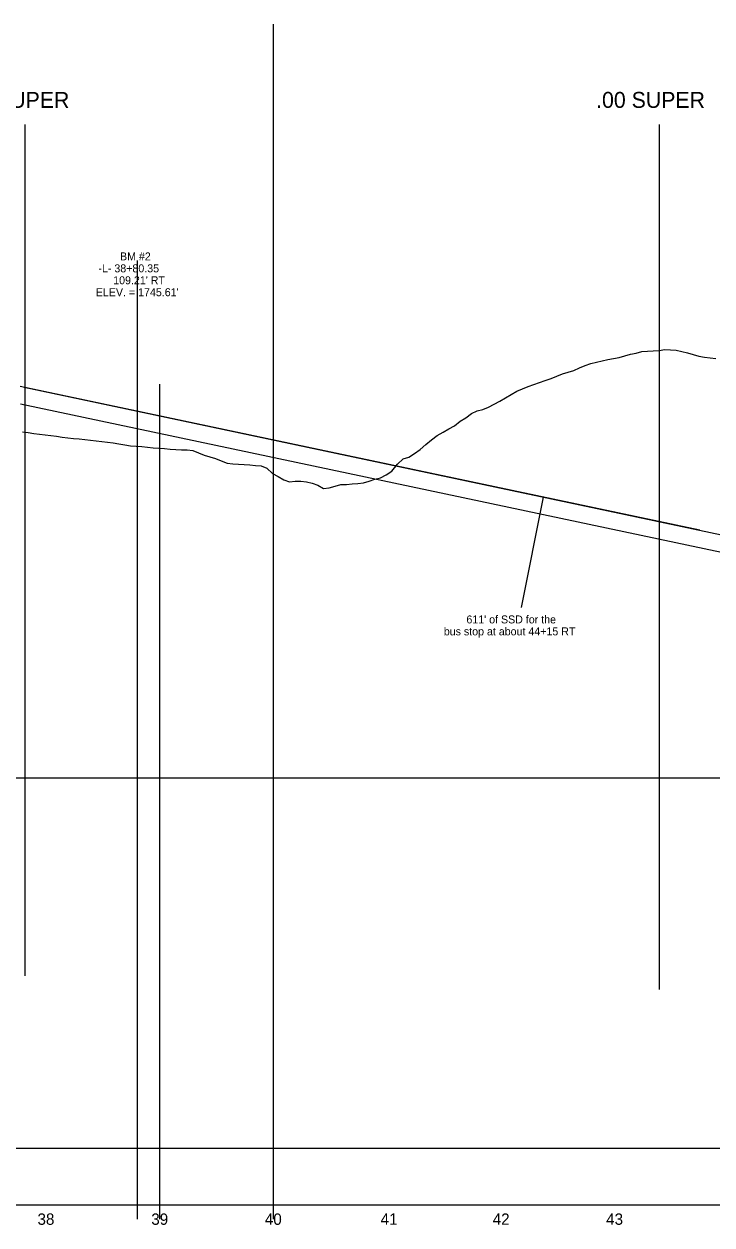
# Model space of a CAD drawing. Extents: x 498575 to 532350, y 405181 to 484585.
# Drawn here: x 508600 to 509205, y 483216 to 484272 of the extents above; entities that cross this region are included whole.
import ezdxf

# ---------------------------------------------------------------- set-up
doc = ezdxf.new("R2010")
doc.units = 0
for name, color, linetype in [('Exist Profile Cell', 7, 'Continuous'), ('Exist Vertical Profile Ground Line', 7, 'Continuous'), ('Exist Vertical Profile Horizontal Axis Label Major', 7, 'Continuous'), ('Prop PFL Text', 7, 'Continuous'), ('Prop Vertical Profile Grade', 7, 'Continuous'), ('Scratch_Level_0', 7, 'Continuous'), ('Scratch_Level_2', 7, 'Continuous'), ('Scratch_Level_4', 7, 'Continuous'), ('Scratch_Level_5', 7, 'Continuous')]:
    doc.layers.add(name, color=color, linetype=linetype)

msp = doc.modelspace()

# ---------------------------------------------------------------- linework, layer by layer
at = {"layer": 'Exist Profile Cell'}
msp.add_line((505856.7, 483233.7), (526056.7, 483233.7), dxfattribs=at)
at = {"layer": 'Exist Vertical Profile Ground Line'}
for points in [[(508813.2, 483881.6), (508818.2, 483876.9), (508823.2, 483874.1), (508828.2, 483871.3), (508833.2, 483869.6), (508838.2, 483870), (508843.2, 483870), (508848.2, 483869.6), (508853.2, 483868.4), (508858.2, 483866.5), (508863.2, 483863.7), (508868.2, 483864.1), (508873.2, 483865.8), (508878.2, 483867), (508883.2, 483867.2), (508888.2, 483867.6), (508893.2, 483868), (508898.2, 483868.7), (508903.2, 483870.2), (508908.2, 483871.7), (508913.2, 483872.9), (508918.2, 483875.6), (508923.2, 483879), (508928.2, 483885.1), (508933.2, 483889.6), (508938.2, 483891.1), (508943.2, 483894.4), (508948.2, 483898), (508953.2, 483902.3), (508958.2, 483906.4), (508963.2, 483910.2), (508968.2, 483913.2), (508973.2, 483916), (508978.2, 483918.7), (508983.2, 483922.8), (508988.2, 483925.7), (508993.2, 483929.7), (508998.2, 483931.9), (509003.2, 483933.1), (509008.2, 483935.1), (509013.2, 483937.8), (509018.2, 483940.4), (509023.2, 483943.4), (509028.2, 483946.2), (509033.2, 483949.2), (509038.2, 483951.4), (509043.2, 483953.4), (509048.2, 483955.2), (509053.2, 483956.9), (509058.2, 483958.6), (509063.2, 483960.3), (509068.2, 483962.5), (509073.2, 483964.4), (509078.2, 483965.9), (509083.2, 483967.5), (509088.2, 483969.8), (509093.2, 483971.9), (509098.2, 483973.4), (509103.2, 483974.7), (509108.2, 483975.8), (509113.2, 483977.1), (509118.2, 483978), (509123.2, 483978.9), (509128.2, 483980.3), (509133.2, 483981.7), (509138.2, 483982.7), (509143.2, 483984.2), (509148.2, 483984.4), (509153.2, 483984.6), (509158.2, 483985.1), (509163.2, 483985.7), (509168.2, 483985.6), (509173.2, 483985.2), (509178.2, 483984.2), (509183.2, 483982.8), (509188.2, 483981.4), (509193.2, 483979.9), (509198.2, 483979), (509203.2, 483978.4), (509208.2, 483977.8)], [(508598.2, 483913.5), (508603.2, 483912.8), (508608.2, 483912.1), (508613.2, 483911.5), (508618.2, 483910.8), (508623.2, 483910.1), (508628.2, 483909.5), (508633.2, 483908.9), (508638.2, 483908.3), (508643.2, 483907.7), (508648.2, 483907.2), (508653.2, 483906.6), (508658.2, 483906.1), (508663.2, 483905.5), (508668.2, 483905), (508673.2, 483904.4), (508678.2, 483903.8), (508683.2, 483902.9), (508688.2, 483901.9), (508693.2, 483901), (508698.2, 483900.7), (508703.2, 483900.6), (508708.2, 483899.9), (508713.2, 483899.4), (508718.2, 483899.1), (508723.2, 483898.7), (508728.2, 483898.3), (508733.2, 483897.9), (508738.2, 483897.6), (508743.2, 483897.5), (508748.2, 483896.9), (508753.2, 483895.1), (508758.2, 483892.8), (508763.2, 483891.6), (508768.2, 483889.9), (508773.2, 483887.9), (508778.2, 483885.9), (508783.2, 483885.3), (508788.2, 483885), (508793.2, 483884.6), (508798.2, 483884.3), (508803.2, 483883.9), (508808.2, 483883.5), (508813.2, 483881.6)]]:
    msp.add_lwpolyline(points, dxfattribs=at)
at = {"layer": 'Prop Vertical Profile Grade'}
msp.add_line((508596.6, 483938), (509361.6, 483776.2), dxfattribs=at)
at = {"layer": 'Scratch_Level_0'}
msp.add_line((508699.4, 483221.2), (508699.4, 484064.2), dxfattribs=at)
at = {"layer": 'Scratch_Level_2'}
for p, q in [((508819.1, 483221.2), (508819.1, 484272)), ((508719.1, 483221.2), (508719.1, 483955.4))]:
    msp.add_line(p, q, dxfattribs=at)
at = {"layer": 'Scratch_Level_4'}
for p, q in [((508600.3, 484183.7), (508600.3, 483435.2)), ((509158.4, 484183.7), (509158.4, 483423)), ((505856.7, 483283.7), (512195.1, 483283.7))]:
    msp.add_line(p, q, dxfattribs=at)
at = {"layer": 'Scratch_Level_5'}
for p, q in [((509194.1, 483827), (508596.3, 483953.4)), ((508599.7, 483952.7), (509364.7, 483790.9)), ((509056.3, 483856.1), (509036.9, 483759.1)), ((513582.6, 483609), (498575.1, 483609))]:
    msp.add_line(p, q, dxfattribs=at)

# ---------------------------------------------------------------- texts
at = {"layer": 'Exist Vertical Profile Horizontal Axis Label Major'}
for s, p in [('38', (508611.5, 483216.2)), ('38', (508611.5, 483216.2)), ('39', (508711.6, 483216.2)), ('39', (508711.6, 483216.2)), ('40', (508811.5, 483216.2)), ('40', (508811.5, 483216.2)), ('41', (508913.3, 483216.2)), ('41', (508913.3, 483216.2)), ('42', (509011.9, 483216.2)), ('42', (509011.9, 483216.2)), ('43', (509111.7, 483216.2)), ('43', (509111.7, 483216.2))]:
    msp.add_text(s, height=10, dxfattribs=at).set_placement(p)
at = {"layer": 'Prop PFL Text'}
for s, p in [('BM #2', (508684.1, 484064.2)), ('-L- 38+80.35', (508665.1, 484053.7)), ("109.21' RT", (508678.1, 484043.2)), ("ELEV. = 1745.61'", (508662.8, 484032.7))]:
    msp.add_text(s, height=7, dxfattribs=at).set_placement(p)
at = {"layer": 'Scratch_Level_4'}
for p in [(508543.8, 484198.3), (509102.9, 484198.3)]:
    msp.add_text('.00 SUPER', height=14, dxfattribs=at).set_placement(p)
at = {"layer": 'Scratch_Level_5'}
for s, p in [('bus stop at about 44+15 RT', (508968.9, 483734.5)), ("611' of SSD for the", (508988.8, 483745))]:
    msp.add_text(s, height=7, dxfattribs=at).set_placement(p)

doc.saveas('drawing.dxf')
